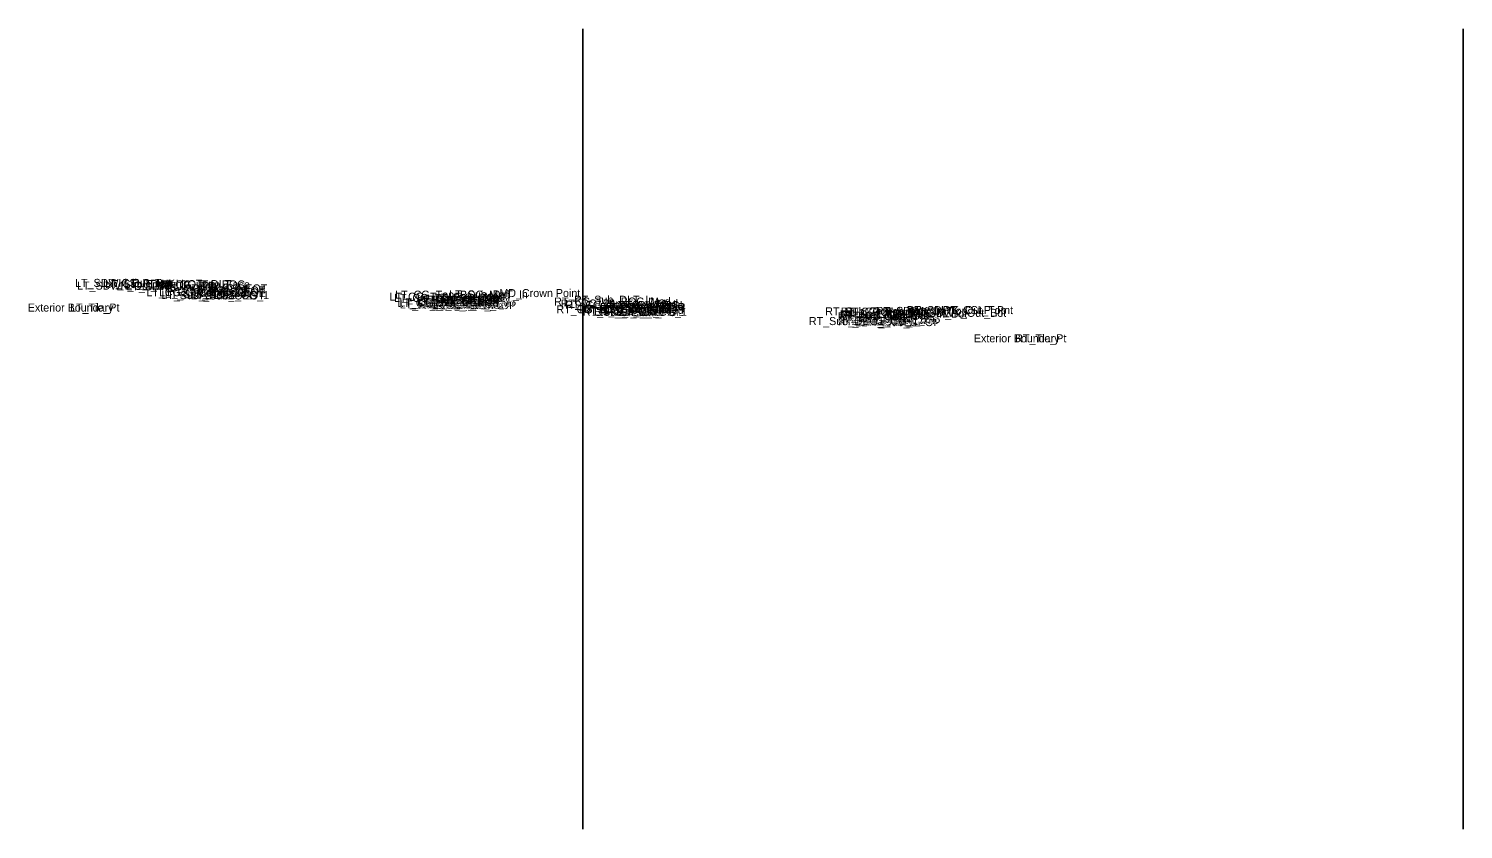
# Model space of a CAD drawing. Extents: x 0 to 6300, y -50 to 9550.
# Drawn here: x 1080.8 to 1260, y 7950 to 8050 of the extents above; entities that cross this region are included whole.
import ezdxf

# ---------------------------------------------------------------- set-up
doc = ezdxf.new("R2010")
doc.units = 0
for name, color, linetype in [('Default', 7, 'Continuous'), ('Prop XS Exc Vertical Line 2', 7, 'Continuous'), ('Prop XS Exc Vertical Line 3', 7, 'Continuous')]:
    doc.layers.add(name, color=color, linetype=linetype)

msp = doc.modelspace()

# ---------------------------------------------------------------- linework, layer by layer
at = {"layer": 'Prop XS Exc Vertical Line 2'}
msp.add_line((1150, 8050), (1150, 7950), dxfattribs=at)
at = {"layer": 'Prop XS Exc Vertical Line 3'}
msp.add_line((1260, 8050), (1260, 7950), dxfattribs=at)

# ---------------------------------------------------------------- texts
at = {"layer": 'Default'}
for s, p in [('LT_SDWK_Out_Top', (1086.58, 8017.75)), ('LT_SDWK_Out_Bot', (1086.83, 8017.41)), ('LT_CSLP_Pnt', (1090.1, 8017.75)), ('LT_Sub_Trench_Out_DLT', (1090.32, 8017.6)), ('LT_SDWK_In_Top', (1092.74, 8017.65)), ('LT_SDWK_In_Bot', (1092.99, 8017.31)), ('LT_CG_Top_BOC', (1096.81, 8017.56)), ('LT_CG_Top_Face', (1097.34, 8017.56)), ('LT_CG1_Shelf_Out', (1095.48, 8016.59)), ('LT_CG_Bot_BOC', (1097.09, 8016.57)), ('LT_Sub_OEOT_CG_1', (1097.36, 8016.22)), ('LT_Sub_OEOP', (1097.79, 8016.35)), ('LT_CG_Top_Gut', (1097.87, 8017.06)), ('LT_PV2_OEOT', (1100.99, 8016.81)), ('LT_PV3_OEOT', (1100.99, 8016.56)), ('LT_Sub_OEOT', (1101.04, 8016.18)), ('LT_PV1_OEOT', (1101.23, 8017.06)), ('LT_CG_Bot_IE', (1101.34, 8016.47)), ('LT_CG_Top_Face_Med', (1125.87, 8016.03)), ('LT_CG_Top_Gut_Med', (1126.42, 8015.87)), ('LT_CG_Top_BOC_Med', (1126.57, 8016.28)), ('LT_CG_Bot_IE_Med', (1127.09, 8015.31)), ('LT_PV2_OEEOP', (1129.29, 8015.65)), ('LT_PV3_OEEOP', (1129.29, 8015.4)), ('LT_PV2_IEEOP', (1130.05, 8015.65)), ('LT_PV2_PGL', (1131.26, 8015.65)), ('LT_PV1_PGL', (1131.5, 8015.9)), ('LT_Sub_DLT_In', (1133.32, 8016.32)), ('MD_Crown Point', (1139.58, 8016.48)), ('RT_CG_Top_BOC_Med', (1146.43, 8015.42)), ('RT_Sub_DLT_In', (1148.91, 8015.65)), ('Exterior Boundary', (1080.67, 8014.67)), ('LT_Tie_Pt', (1085.95, 8014.67)), ('LT_CG_Bot_BOC_Med', (1126.85, 8015.25)), ('LT_Sub_IEOT_CG_1', (1127.13, 8015.06)), ('LT_Sub_OEEOP', (1129.33, 8015.02)), ('LT_Sub_IEEOP', (1130.09, 8015.02)), ('LT_CG1_Shelf_In', (1130.71, 8015.23)), ('LT_Sub_PGL', (1131.31, 8015.02)), ('LT_Sub_IEOP', (1133.06, 8014.97)), ('RT_CG_Bot_BOC_Med', (1146.71, 8014.45)), ('RT_CG_Top_Face_Med', (1147.25, 8015.17)), ('RT_CG_Top_Gut_Med', (1147.8, 8015.01)), ('RT_CG1_Shelf_In', (1149.57, 8014.47)), ('RT_CG_Bot_IE_Med', (1149.98, 8014.39)), ('RT_Sub_IEOT_CG_1', (1150.01, 8014.14)), ('RT_Sub_IEOP', (1151.42, 8014.23)), ('RT_PV2_OEEOP', (1152.17, 8014.73)), ('RT_PV3_OEEOP', (1152.17, 8014.48)), ('RT_Sub_OEEOP', (1152.21, 8014.1)), ('RT_PV2_IEEOP', (1152.93, 8014.73)), ('RT_Sub_IEEOP', (1152.97, 8014.1)), ('RT_PV2_PGL', (1154.15, 8014.73)), ('RT_Sub_PGL', (1154.19, 8014.1)), ('RT_PV1_PGL', (1154.38, 8014.98)), ('RT_Sub_Trench_Out_DLT', (1180.29, 8014.2)), ('RT_PV2_OEOT', (1181.87, 8013.57)), ('RT_PV1_OEOT', (1182.11, 8013.82)), ('RT_CG_Top_Face', (1182.22, 8014.16)), ('RT_CG_Top_BOC', (1182.69, 8014.16)), ('RT_CG_Top_Gut', (1182.75, 8013.66)), ('RT_SDWK_In_Top', (1186.62, 8014.25)), ('RT_SDWK_In_Bot', (1186.87, 8013.91)), ('RT_SDWK_Out_Top', (1190.46, 8014.35)), ('RT_SDWK_Out_Bot', (1190.71, 8014.01)), ('RT_CSLP_Pnt', (1194.98, 8014.35)), ('RT_Sub_OEOT_CG_1', (1178.25, 8012.98)), ('RT_PV3_OEOT', (1181.87, 8013.32)), ('RT_Sub_OEOT', (1181.92, 8012.94)), ('RT_CG_Bot_IE', (1182.22, 8013.23)), ('RT_CG1_Shelf_Out', (1182.36, 8013.11)), ('RT_CG_Bot_BOC', (1182.97, 8013.13)), ('RT_Sub_OEOP', (1185.17, 8012.85)), ('Exterior Boundary', (1198.86, 8010.83)), ('RT_Tie_Pt', (1204.02, 8010.83))]:
    msp.add_text(s, height=1, dxfattribs=at).set_placement(p)

doc.saveas('drawing.dxf')
